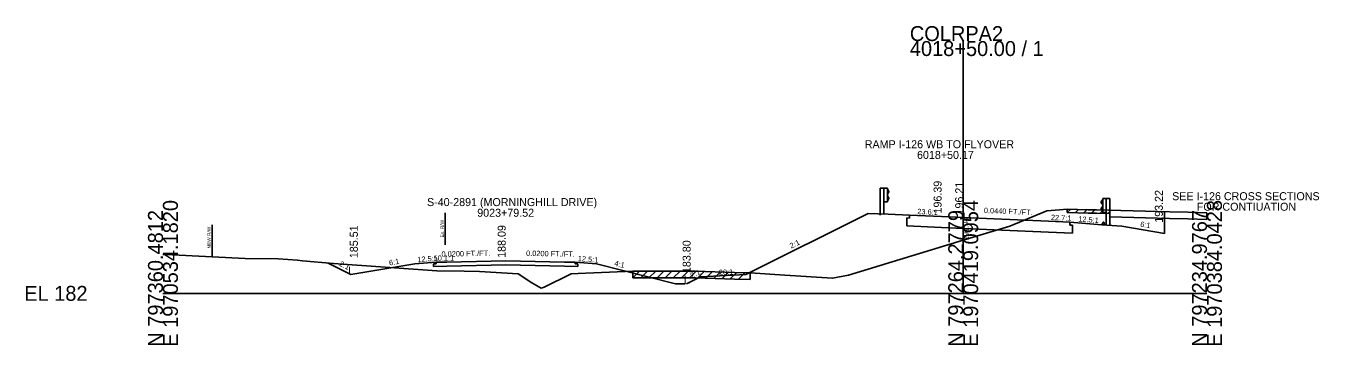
# Model space of a CAD drawing. Extents: x -26 to 1971083, y -10 to 798159.
# Drawn here: x -25.7 to 216.7, y 2990.3 to 3050.1 of the extents above; entities that cross this region are included whole.
import ezdxf

# ---------------------------------------------------------------- set-up
doc = ezdxf.new("R2010")
doc.units = 0
for name, color, linetype in [('RD_GPK_XS_Cell', 7, 'Continuous'), ('RD_XS_Base', 7, 'Continuous'), ('RD_XS_CurbTop', 7, 'Continuous'), ('RD_XS_EarthShd', 7, 'Continuous'), ('RD_XS_ExGround', 7, 'Continuous'), ('RD_XS_ExPaveRet', 7, 'Continuous'), ('RD_XS_ExRW', 7, 'Continuous'), ('RD_XS_GR', 7, 'Continuous'), ('RD_XS_Misc_Line', 7, 'Continuous'), ('RD_XS_NewRW', 7, 'Continuous'), ('RD_XS_Pave', 7, 'Continuous'), ('RD_XS_PaveShd', 7, 'Continuous'), ('RD_XS_TieSlope', 7, 'Continuous'), ('RD_XS_TX_Elev_EX', 7, 'Continuous'), ('RD_XS_TX_Elev_PR', 7, 'Continuous'), ('RD_XS_TX_Misc', 7, 'Continuous'), ('RD_XS_TX_MkPT', 7, 'Continuous'), ('RD_XS_TX_Notes', 7, 'Continuous'), ('RD_XS_TX_Profile', 7, 'Continuous'), ('RD_XS_TX_ShdSlope', 7, 'Continuous'), ('RD_XS_TX_Slope', 7, 'Continuous'), ('RD_XS_TX_Station', 7, 'Continuous')]:
    doc.layers.add(name, color=color, linetype=linetype)

msp = doc.modelspace()

# ---------------------------------------------------------------- linework, layer by layer
at = {"layer": 'RD_GPK_XS_Cell'}
for p, q in [((150, 3000), (150, 3047.24)), ((0, 3000), (150, 3000)), ((150, 3000), (195.69, 3000))]:
    msp.add_line(p, q, dxfattribs=at)
at = {"layer": 'RD_XS_Base'}
for p, q in [((139.44, 3014.11), (139.94, 3014.09)), ((139.44, 3012.63), (139.44, 3014.11)), ((139.94, 3014.09), (139.94, 3014.65)), ((170, 3012.77), (170, 3013.33)), ((145.95, 3012.35), (139.44, 3012.63)), ((145.95, 3012.35), (150, 3012.17)), ((150, 3012.17), (166, 3011.47)), ((166, 3011.47), (170.5, 3011.27)), ((170.5, 3012.75), (170, 3012.77)), ((170.5, 3011.27), (170.5, 3012.75)), ((50.74, 3005.52), (51.24, 3005.53)), ((50.74, 3005.04), (50.74, 3005.52)), ((53.24, 3005.09), (50.74, 3005.04)), ((51.24, 3005.53), (51.24, 3005.83)), ((53.24, 3005.09), (64.24, 3005.31)), ((64.24, 3005.31), (75.24, 3005.09)), ((75.24, 3005.09), (77.74, 3005.04)), ((77.24, 3005.53), (77.24, 3005.83)), ((77.74, 3005.52), (77.24, 3005.53)), ((77.74, 3005.04), (77.74, 3005.52))]:
    msp.add_line(p, q, dxfattribs=at)
at = {"layer": 'RD_XS_CurbTop'}
for p, q in [((176, 3012.85), (176.25, 3013.31)), ((176.47, 3012.82), (176.41, 3013.25)), ((176, 3012.85), (176.47, 3012.82))]:
    msp.add_line(p, q, dxfattribs=at)
msp.add_ellipse((176.32, 3013.23), major_axis=(0, -0.131), ratio=0.686, start_param=1.762783, end_param=4.036677, dxfattribs=at)
at = {"layer": 'RD_XS_EarthShd'}
for p, q in [((139.94, 3014.65), (135.93, 3014.82)), ((170, 3013.33), (176, 3012.85)), ((51.24, 3005.83), (47.24, 3005.51)), ((77.24, 3005.83), (81.24, 3005.51))]:
    msp.add_line(p, q, dxfattribs=at)
at = {"layer": 'RD_XS_ExGround'}
msp.add_lwpolyline([(0, 3007.3), (1.77, 3007.19), (15.4, 3006.54), (21.62, 3006.49), (25.22, 3006.19), (26.16, 3006.1), (31.94, 3005.56), (51.35, 3004.2), (56.47, 3004.14), (59.33, 3004.07), (66.58, 3003.65), (69.15, 3001.98), (70.87, 3000.97), (71.45, 3001.17), (76.51, 3003.67), (77.83, 3003.71), (88.05, 3004.18), (97.18, 3004.16), (99.81, 3004.15), (107.11, 3003.93), (110.05, 3003.84), (116.56, 3003.42), (125.51, 3002.82), (128.47, 3003.42), (150, 3009.94), (158.77, 3012.59), (165.7, 3015.48), (168.03, 3015.65), (169.49, 3015.75), (173.45, 3015.63), (174.99, 3015.61), (188.7, 3015.27), (192.14, 3015.19), (195.69, 3015.07)], dxfattribs=at)
at = {"layer": 'RD_XS_ExPaveRet'}
for p, q in [((169.49, 3015.12), (169.49, 3015.75)), ((177.51, 3015.55), (177.51, 3014.3)), ((169.49, 3015.12), (173.45, 3015)), ((173.45, 3015), (174.99, 3014.99)), ((174.99, 3014.99), (177.51, 3014.93)), ((195.69, 3015.07), (195.64, 3013.82)), ((88.05, 3002.93), (88.05, 3004.18)), ((110.05, 3003.84), (110.05, 3002.59)), ((88.05, 3002.93), (97.18, 3002.91)), ((97.18, 3002.91), (99.81, 3002.9)), ((99.81, 3002.9), (107.11, 3002.68)), ((107.11, 3002.68), (110.05, 3002.59))]:
    msp.add_line(p, q, dxfattribs=at)
msp.add_lwpolyline([(177.51, 3014.3), (188.67, 3014.03), (192.1, 3013.94), (195.64, 3013.82)], dxfattribs=at)
at = {"layer": 'RD_XS_ExRW'}
msp.add_line((52.9, 3015.08), (52.9, 3009.08), dxfattribs=at)
at = {"layer": 'RD_XS_GR'}
for p, q in [((135.12, 3019.69), (134.45, 3019.69)), ((134.45, 3019.69), (134.45, 3014.64)), ((135.78, 3019.69), (135.12, 3019.69)), ((135.12, 3019.69), (135.12, 3014.75)), ((135.78, 3017.12), (135.78, 3019.69)), ((135.78, 3019.53), (136.05, 3019.09)), ((136.05, 3018.98), (135.78, 3018.54)), ((136.05, 3017.84), (135.78, 3018.28)), ((136.05, 3019.09), (136.05, 3018.98)), ((135.78, 3017.12), (135.12, 3017.12)), ((135.78, 3017.29), (136.05, 3017.73)), ((136.05, 3017.73), (136.05, 3017.84)), ((176.15, 3017.57), (175.88, 3017.13)), ((175.88, 3017.13), (175.88, 3017.02)), ((175.88, 3017.02), (176.15, 3016.58)), ((175.88, 3015.87), (176.15, 3016.31)), ((175.88, 3015.76), (175.88, 3015.87)), ((176.15, 3015.32), (175.88, 3015.76)), ((176.15, 3017.73), (176.81, 3017.73)), ((176.15, 3015.16), (176.15, 3017.73)), ((176.81, 3017.73), (177.48, 3017.73)), ((176.81, 3017.73), (176.81, 3012.79)), ((177.48, 3017.73), (177.48, 3012.68)), ((176.15, 3015.16), (176.81, 3015.16))]:
    msp.add_line(p, q, dxfattribs=at)
at = {"layer": 'RD_XS_Misc_Line'}
for p, q in [((169.49, 3015.12), (170.1, 3015.73)), ((171.01, 3015.08), (171.63, 3015.68)), ((172.53, 3015.03), (173.15, 3015.64)), ((174.05, 3015), (174.68, 3015.62)), ((175.58, 3014.97), (176.2, 3015.58)), ((177.1, 3014.94), (177.51, 3015.34)), ((88.05, 3002.93), (89.31, 3004.18)), ((89.57, 3002.93), (90.84, 3004.18)), ((91.09, 3002.93), (92.36, 3004.17)), ((92.62, 3002.92), (93.88, 3004.17)), ((94.14, 3002.92), (95.41, 3004.17)), ((95.66, 3002.92), (96.93, 3004.16)), ((97.19, 3002.91), (98.45, 3004.16)), ((98.71, 3002.91), (99.97, 3004.15)), ((100.23, 3002.89), (101.46, 3004.1)), ((101.75, 3002.84), (102.98, 3004.06)), ((103.28, 3002.8), (104.51, 3004.01)), ((104.8, 3002.75), (106.03, 3003.96)), ((106.32, 3002.7), (107.55, 3003.92)), ((107.85, 3002.66), (109.08, 3003.87))]:
    msp.add_line(p, q, dxfattribs=at)
at = {"layer": 'RD_XS_NewRW'}
msp.add_line((9.24, 3012.83), (9.24, 3006.83), dxfattribs=at)
at = {"layer": 'RD_XS_Pave'}
for p, q in [((145.95, 3014.39), (150, 3014.21)), ((150, 3014.21), (166, 3013.51)), ((53.24, 3005.87), (64.24, 3006.09)), ((64.24, 3006.09), (75.24, 3005.87))]:
    msp.add_line(p, q, dxfattribs=at)
at = {"layer": 'RD_XS_PaveShd'}
for p, q in [((145.95, 3014.39), (139.94, 3014.65)), ((166, 3013.51), (170, 3013.33)), ((53.24, 3005.87), (51.24, 3005.83)), ((75.24, 3005.87), (77.24, 3005.83))]:
    msp.add_line(p, q, dxfattribs=at)
at = {"layer": 'RD_XS_TieSlope'}
for p, q in [((132.17, 3014.98), (109.24, 3003.53)), ((135.93, 3014.82), (132.17, 3014.98)), ((187.75, 3011.22), (187.75, 3015.3)), ((176, 3012.85), (179.75, 3012.55)), ((179.75, 3012.55), (187.75, 3011.22)), ((35.22, 3003.51), (30.94, 3005.65)), ((47.24, 3005.51), (35.22, 3003.51)), ((81.24, 3005.51), (96.1, 3001.8)), ((100.77, 3003.11), (109.24, 3003.53)), ((96.1, 3001.8), (97.9, 3001.8)), ((100.77, 3003.11), (98.16, 3001.8))]:
    msp.add_line(p, q, dxfattribs=at)

# ---------------------------------------------------------------- texts
at = {"layer": 'RD_GPK_XS_Cell'}
for s, p in [('COLRPA2', (140, 3047.24)), ('4018+50.00 / 1', (140, 3044.44)), ('EL 182', (-26, 2998.6))]:
    msp.add_text(s, height=2.8, dxfattribs=at).set_placement(p)
for s, p in [('E 1970534.1820', (2.8, 2990)), ('E 1970419.0954', (152.8, 2990)), ('E 1970384.0428', (198.49, 2990)), ('N 797360.4812', (0, 2990)), ('N 797264.2779', (150, 2990)), ('N 797234.9767', (195.69, 2990))]:
    msp.add_text(s, height=2.8, rotation=90, dxfattribs=at).set_placement(p)
at = {"layer": 'RD_XS_ExRW'}
msp.add_text('Ex. R/W ', height=0.65, rotation=90, dxfattribs=at).set_placement((52.65, 3010.47))
at = {"layer": 'RD_XS_NewRW'}
msp.add_text('NEW R/W ', height=0.65, rotation=90, dxfattribs=at).set_placement((8.97, 3008.39))
at = {"layer": 'RD_XS_TX_Elev_EX'}
msp.add_text('191.94', height=1, rotation=90, dxfattribs=at).set_placement((151, 3009.94))
at = {"layer": 'RD_XS_TX_Elev_PR'}
for s, p in [(' 196.39', (145.95, 3014.39)), (' 196.21', (150, 3014.21)), (' 188.09', (64.24, 3006.09))]:
    msp.add_text(s, height=1.5, rotation=90, dxfattribs=at).set_placement(p)
at = {"layer": 'RD_XS_TX_Misc'}
for s, p in [('193.22', (187.42, 3013.22)), ('185.51', (36.53, 3006.59)), ('183.80', (98.91, 3003.8))]:
    msp.add_text(s, height=1.5, rotation=90, dxfattribs=at).set_placement(p)
at = {"layer": 'RD_XS_TX_MkPT'}
for p in [(34.71, 3003.51), (97.65, 3001.8)]:
    msp.add_text('L', height=1.5, dxfattribs=at).set_placement(p)
at = {"layer": 'RD_XS_TX_Notes'}
for s, p in [('SEE I-126 CROSS SECTIONS', (189.16, 3017.44)), ('FOR CONTIUATION', (193.79, 3015.47))]:
    msp.add_text(s, height=1.5, dxfattribs=at).set_placement(p)
at = {"layer": 'RD_XS_TX_Profile'}
msp.add_text('50.1:1', height=1, rotation=1.1444, dxfattribs=at).set_placement((50.75, 3006.07))
at = {"layer": 'RD_XS_TX_ShdSlope'}
for rotation, p in [(355.4261, (171.54, 3013.46)), (4.5739, (47.74, 3005.81)), (355.4323, (77.73, 3006.05))]:
    msp.add_text('12.5:1', height=1, rotation=rotation, dxfattribs=at).set_placement(p)
at = {"layer": 'RD_XS_TX_Slope'}
for s, rotation, p in [('23.6:1', 357.5744, (141.38, 3014.84)), ('0.0440 FT./FT.', 357.4806, (153.86, 3015.05)), ('22.7:1', 357.4806, (166.43, 3013.74)), ('6:1', 350.5377, (183.13, 3012.5)), ('2:1', 26.5201, (117.78, 3008.36)), ('2:1', 333.444, (32.97, 3005.2)), ('6:1', 9.4623, (42.46, 3005.22)), ('0.0200 FT./FT.', 1.1444, (52.22, 3006.85)), ('0.0200 FT./FT.', 358.8529, (68.06, 3007.02)), ('4:1', 345.971, (84.54, 3005.2)), ('2:1', 26.5651, (99.15, 3002.79)), ('20:1', 2.8624, (104.23, 3003.4))]:
    msp.add_text(s, height=1, rotation=rotation, dxfattribs=at).set_placement(p)
at = {"layer": 'RD_XS_TX_Station'}
for s, p in [('RAMP I-126 WB TO FLYOVER', (131.55, 3027.17)), ('6018+50.17', (141.34, 3025.17)), ('S-40-2891 (MORNINGHILL DRIVE)', (49.5, 3016.34)), ('9023+79.52', (58.91, 3014.34))]:
    msp.add_text(s, height=1.5, dxfattribs=at).set_placement(p)

doc.saveas('drawing.dxf')
